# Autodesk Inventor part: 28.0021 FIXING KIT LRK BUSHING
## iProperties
Created: 2007-04
Part Number: 28.0021 FIXING KIT LRK BUSHING
Document SubType Name: Modeling
Designer: Andy Moles
Material: Steel
Mass: 35.6439 g
Surface Area: 22.99 cm^2
Volume: 4.54063 cm^3
Density: 7.85 g/cm^3
Author: Andy Moles
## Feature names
1. Extrusion1
2. Extrusion2
3. Extrusion3
4. Extrusion4
5. Chamfer1
